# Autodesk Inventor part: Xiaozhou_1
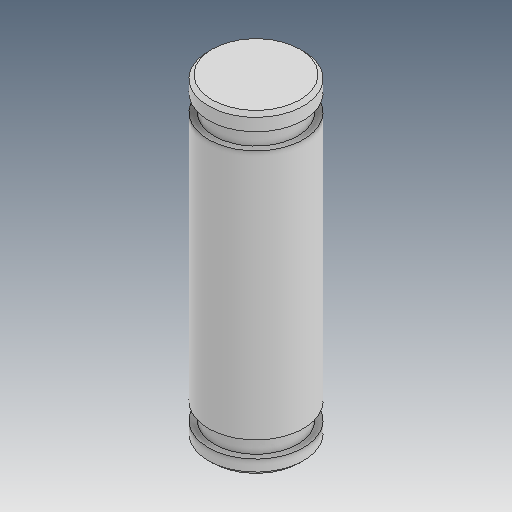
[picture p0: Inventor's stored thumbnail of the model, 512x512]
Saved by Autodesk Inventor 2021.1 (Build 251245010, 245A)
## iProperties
Created: 2019-04
Part Number: Xiaozhou_1
Material: Ogólny
Document SubType Name: Modeling
Designer: user
Density: 1 g/cm^3
Appearance: Domyślna
Author: user
Revision Number: ÈÎºÎ
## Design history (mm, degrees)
feature "ÊäÈë1"
node "Bryła1"
